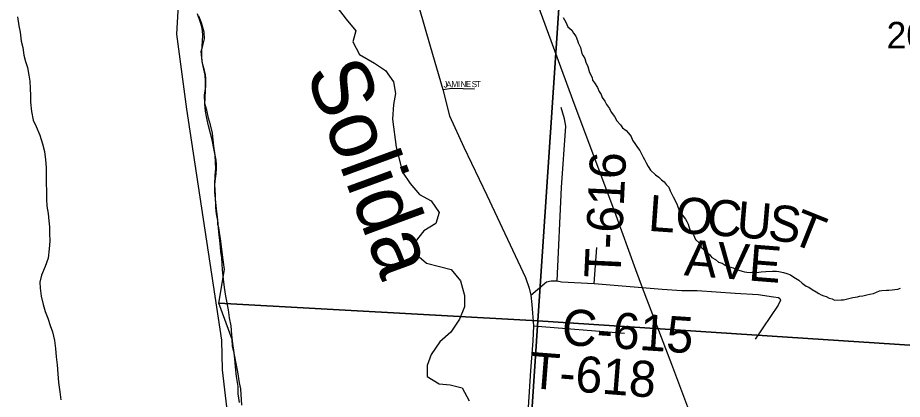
# Model space of a CAD drawing. Extents: x 1949938.81 to 1949945.61, y 152207.65 to 152214.09.
# Drawn here: x 1949939.476 to 1949940.868, y 152211.171 to 152211.771 of the extents above; entities that cross this region are included whole.
import ezdxf

# ---------------------------------------------------------------- set-up
doc = ezdxf.new("R2010")
doc.units = 0
for name, color, linetype in [('GM_X_County', 7, 'Continuous'), ('GM_X_County_Road', 7, 'Continuous'), ('GM_X_County_Road_Text', 7, 'Continuous'), ('GM_X_Major_River', 7, 'Continuous'), ('GM_X_Minor_River', 7, 'Continuous'), ('GM_X_Minor_River_Text', 7, 'Continuous'), ('GM_X_Section', 7, 'Continuous'), ('GM_X_Section_Text', 7, 'Continuous'), ('GM_X_Township', 7, 'Continuous'), ('GM_X_Township_Road', 7, 'Continuous'), ('GM_X_Township_Road_Text', 7, 'Continuous'), ('GM_X_Township_Subdivision', 7, 'Continuous'), ('GM_X_Township_Subdivision_Text', 7, 'Continuous'), ('GM_X_US_Route', 7, 'Continuous')]:
    doc.layers.add(name, color=color, linetype=linetype)

msp = doc.modelspace()

# ---------------------------------------------------------------- linework, layer by layer
at = {"layer": 'GM_X_County'}
msp.add_lwpolyline([(1949939.7311, 152211.8376), (1949939.7258, 152211.7457), (1949939.7413, 152211.6273), (1949939.7962, 152211.2639), (1949939.7977, 152211.2171), (1949939.8117, 152211.0959), (1949939.8776, 152210.6025), (1949939.8931, 152210.4482), (1949939.9215, 152210.363), (1949939.9378, 152210.2911), (1949940.0851, 152209.7125), (1949940.1207, 152209.6209), (1949940.3383, 152209.2145), (1949940.3947, 152209.1158)], dxfattribs=at)
at = {"layer": 'GM_X_County_Road'}
for points in [[(1949940.0902, 152211.8474), (1949940.1245, 152211.7264), (1949940.1446, 152211.6586), (1949940.1553, 152211.6171), (1949940.1779, 152211.5675), (1949940.2141, 152211.4924), (1949940.2747, 152211.3627), (1949940.2807, 152211.3456), (1949940.2832, 152211.3349), (1949940.2845, 152211.32), (1949940.2871, 152211.2866), (1949940.2865, 152211.2628), (1949940.2824, 152211.2159), (1949940.2737, 152211.0767), (1949940.2714, 152211.0147), (1949940.2658, 152210.896)], [(1949940.2832, 152211.3349), (1949940.3076, 152211.3557), (1949940.3151, 152211.3576), (1949940.3248, 152211.3574), (1949940.3316, 152211.3557), (1949940.3825, 152211.3532), (1949940.4583, 152211.3469)]]:
    msp.add_lwpolyline(points, dxfattribs=at)
at = {"layer": 'GM_X_Major_River'}
for points in [[(1949939.4757, 152211.7727), (1949939.4776, 152211.7586), (1949939.4795, 152211.7488), (1949939.4814, 152211.7344), (1949939.4837, 152211.7245), (1949939.4856, 152211.7127), (1949939.4882, 152211.7025), (1949939.4912, 152211.693), (1949939.4935, 152211.6812), (1949939.4946, 152211.6714), (1949939.4954, 152211.66), (1949939.4958, 152211.649), (1949939.4958, 152211.6384), (1949939.4976, 152211.6236), (1949939.5003, 152211.6103), (1949939.5048, 152211.6004), (1949939.5105, 152211.5867), (1949939.5146, 152211.5731), (1949939.5177, 152211.5609), (1949939.5196, 152211.5476), (1949939.5203, 152211.5359), (1949939.5203, 152211.5256), (1949939.5207, 152211.5097), (1949939.5211, 152211.4998), (1949939.5211, 152211.4865), (1949939.5218, 152211.4751), (1949939.5237, 152211.4634), (1949939.5248, 152211.452), (1949939.5256, 152211.4425), (1949939.526, 152211.4323), (1949939.5263, 152211.4197), (1949939.5252, 152211.4076), (1949939.5237, 152211.3932), (1949939.5191, 152211.3799), (1949939.5131, 152211.3662), (1949939.5108, 152211.3552), (1949939.5112, 152211.3457), (1949939.5127, 152211.3332), (1949939.5157, 152211.3199), (1949939.5191, 152211.3093), (1949939.5233, 152211.2986), (1949939.5271, 152211.2869), (1949939.5305, 152211.277), (1949939.5335, 152211.2637), (1949939.5354, 152211.2508), (1949939.5365, 152211.2379), (1949939.5376, 152211.2253), (1949939.5388, 152211.2109), (1949939.5399, 152211.1976), (1949939.5418, 152211.1828), (1949939.5437, 152211.1703)], [(1949939.8246, 152211.166), (1949939.8227, 152211.1793), (1949939.8224, 152211.1911), (1949939.8201, 152211.207), (1949939.8186, 152211.2218), (1949939.8175, 152211.2347), (1949939.8156, 152211.248), (1949939.8144, 152211.2587), (1949939.8129, 152211.2723), (1949939.8114, 152211.2868), (1949939.8092, 152211.2989), (1949939.8073, 152211.3118), (1949939.8031, 152211.3335), (1949939.8009, 152211.3471), (1949939.7993, 152211.36), (1949939.7982, 152211.3745), (1949939.7967, 152211.3934), (1949939.7956, 152211.4033), (1949939.7941, 152211.4162), (1949939.7922, 152211.4344), (1949939.7914, 152211.4477), (1949939.7903, 152211.458), (1949939.7888, 152211.4705), (1949939.7876, 152211.4804), (1949939.7861, 152211.4974), (1949939.7858, 152211.5092), (1949939.7865, 152211.5229), (1949939.7873, 152211.5343), (1949939.7869, 152211.5441), (1949939.7862, 152211.5551), (1949939.7846, 152211.5692), (1949939.7835, 152211.579), (1949939.782, 152211.5897), (1949939.779, 152211.6026), (1949939.776, 152211.6132), (1949939.7733, 152211.6257), (1949939.7703, 152211.6364), (1949939.7695, 152211.6493), (1949939.7711, 152211.6599), (1949939.7714, 152211.6716), (1949939.7707, 152211.6811), (1949939.7688, 152211.6906), (1949939.7661, 152211.7024), (1949939.7646, 152211.7183), (1949939.7673, 152211.7278), (1949939.7696, 152211.7384), (1949939.7692, 152211.7487), (1949939.765, 152211.7635), (1949939.7609, 152211.7741)]]:
    msp.add_lwpolyline(points, dxfattribs=at)
at = {"layer": 'GM_X_Minor_River'}
for points in [[(1949939.9784, 152211.7876), (1949939.9927, 152211.7693), (1949940.0077, 152211.751), (1949940.0031, 152211.7335), (1949940.0136, 152211.7138), (1949940.0371, 152211.7), (1949940.0544, 152211.6885), (1949940.0672, 152211.6703), (1949940.0702, 152211.652), (1949940.0671, 152211.6346), (1949940.0655, 152211.6118), (1949940.0714, 152211.5677), (1949940.081, 152211.5282), (1949940.0931, 152211.5107), (1949940.1082, 152211.4931), (1949940.1263, 152211.4832), (1949940.1391, 152211.4649), (1949940.1337, 152211.4474), (1949940.1147, 152211.4361), (1949940.101, 152211.4187), (1949940.1002, 152211.4012), (1949940.1191, 152211.3852), (1949940.1395, 152211.3798), (1949940.1577, 152211.3752), (1949940.1727, 152211.3576), (1949940.1787, 152211.3341), (1949940.1786, 152211.3166), (1949940.171, 152211.2969), (1949940.1573, 152211.2764), (1949940.1398, 152211.2613), (1949940.1261, 152211.2416), (1949940.1199, 152211.2241), (1949940.1199, 152211.2066), (1949940.1387, 152211.1952), (1949940.1562, 152211.1936), (1949940.1751, 152211.1889), (1949940.1863, 152211.1684)], [(1949940.3338, 152211.7719), (1949940.3382, 152211.7642), (1949940.3415, 152211.7573), (1949940.3475, 152211.7519), (1949940.3501, 152211.7469), (1949940.3541, 152211.7423), (1949940.3563, 152211.7358), (1949940.3574, 152211.732), (1949940.361, 152211.7243), (1949940.3635, 152211.7151), (1949940.3653, 152211.7117), (1949940.3679, 152211.7071), (1949940.3697, 152211.7013), (1949940.373, 152211.6948), (1949940.3755, 152211.6853), (1949940.3795, 152211.6772), (1949940.3802, 152211.6734), (1949940.3832, 152211.6692), (1949940.3879, 152211.6615), (1949940.3905, 152211.6554), (1949940.3938, 152211.6508), (1949940.3956, 152211.6458), (1949940.3997, 152211.64), (1949940.4022, 152211.6347), (1949940.4071, 152211.6285), (1949940.4096, 152211.6228), (1949940.4148, 152211.6162), (1949940.4185, 152211.6093), (1949940.424, 152211.6028), (1949940.4274, 152211.5982), (1949940.433, 152211.5939), (1949940.4367, 152211.5896), (1949940.4411, 152211.5846), (1949940.4433, 152211.5785), (1949940.4477, 152211.572), (1949940.4507, 152211.567), (1949940.4544, 152211.5624), (1949940.4566, 152211.5585), (1949940.4599, 152211.552), (1949940.4621, 152211.5485), (1949940.4646, 152211.5428), (1949940.4676, 152211.5371), (1949940.4713, 152211.5313), (1949940.4795, 152211.5243), (1949940.4843, 152211.5204), (1949940.4888, 152211.5162), (1949940.4929, 152211.5131), (1949940.4959, 152211.5092), (1949940.5, 152211.5046), (1949940.5021, 152211.4988), (1949940.5069, 152211.4896), (1949940.5095, 152211.485), (1949940.5131, 152211.477), (1949940.5164, 152211.4682), (1949940.523, 152211.4593), (1949940.5264, 152211.4543), (1949940.5286, 152211.4509), (1949940.5308, 152211.4463)], [(1949940.5308, 152211.4463), (1949940.5333, 152211.4375), (1949940.5388, 152211.4298), (1949940.5421, 152211.4225), (1949940.5473, 152211.4175), (1949940.5517, 152211.4098), (1949940.5569, 152211.4056), (1949940.561, 152211.4013), (1949940.5648, 152211.3982), (1949940.5681, 152211.394), (1949940.5737, 152211.3912), (1949940.5786, 152211.3869), (1949940.5842, 152211.3853), (1949940.5891, 152211.3822), (1949940.5959, 152211.3794), (1949940.6015, 152211.3778), (1949940.6102, 152211.3742), (1949940.6154, 152211.3726), (1949940.6192, 152211.3714), (1949940.623, 152211.371), (1949940.6294, 152211.3705), (1949940.6344, 152211.3708), (1949940.6378, 152211.3707), (1949940.6419, 152211.371), (1949940.6453, 152211.3714), (1949940.6526, 152211.372), (1949940.6632, 152211.3726), (1949940.6696, 152211.3725), (1949940.6734, 152211.372), (1949940.6809, 152211.3707), (1949940.6858, 152211.3688), (1949940.6915, 152211.3668), (1949940.6971, 152211.3629), (1949940.7046, 152211.3582), (1949940.7098, 152211.3539), (1949940.7165, 152211.3489), (1949940.7207, 152211.3473), (1949940.7255, 152211.3438), (1949940.7319, 152211.3402), (1949940.7364, 152211.3375), (1949940.7398, 152211.3355), (1949940.7443, 152211.3336), (1949940.7477, 152211.3327), (1949940.7526, 152211.33), (1949940.7571, 152211.3288), (1949940.7609, 152211.3272), (1949940.7715, 152211.3274), (1949940.7749, 152211.3277), (1949940.7836, 152211.3295), (1949940.7897, 152211.3313), (1949940.7969, 152211.3323), (1949940.8004, 152211.3334), (1949940.8057, 152211.334), (1949940.8118, 152211.3351), (1949940.8167, 152211.3365), (1949940.822, 152211.3375), (1949940.827, 152211.3394), (1949940.8316, 152211.3416), (1949940.8354, 152211.3423), (1949940.8429, 152211.3429), (1949940.8464, 152211.3428), (1949940.8517, 152211.3431), (1949940.8558, 152211.3438), (1949940.8604, 152211.3445), (1949940.8646, 152211.3456)]]:
    msp.add_lwpolyline(points, dxfattribs=at)
at = {"layer": 'GM_X_Section'}
for points in [[(1949940.3609, 152212.2864), (1949940.2943, 152211.2945), (1949939.792, 152211.3222), (1949939.8011, 152211.3752), (1949939.7992, 152211.3903), (1949939.7947, 152211.4237), (1949939.7935, 152211.4332), (1949939.792, 152211.4407), (1949939.7909, 152211.446), (1949939.7905, 152211.4521), (1949939.7886, 152211.4627), (1949939.7875, 152211.4729), (1949939.7868, 152211.4923), (1949939.786, 152211.5086), (1949939.7864, 152211.5142), (1949939.7879, 152211.5256), (1949939.7883, 152211.5343), (1949939.7883, 152211.5408), (1949939.7879, 152211.5472), (1949939.7857, 152211.5578), (1949939.7845, 152211.5658), (1949939.7815, 152211.5794), (1949939.7762, 152211.6014), (1949939.774, 152211.6105), (1949939.7728, 152211.6158), (1949939.7713, 152211.6245), (1949939.7702, 152211.6359), (1949939.7706, 152211.6446), (1949939.771, 152211.6582), (1949939.7717, 152211.6643), (1949939.7717, 152211.6707), (1949939.7717, 152211.676), (1949939.771, 152211.6817), (1949939.7695, 152211.6885), (1949939.7668, 152211.698), (1949939.7661, 152211.7033), (1949939.7657, 152211.7098), (1949939.7657, 152211.7181), (1949939.7669, 152211.7431), (1949939.7665, 152211.7514), (1949939.7657, 152211.7571), (1949939.7635, 152211.7639), (1949939.7589, 152211.7776)], [(1949939.8282, 152211.1619), (1949939.8267, 152211.1872), (1949939.8248, 152211.1967), (1949939.8222, 152211.2142), (1949939.8196, 152211.2274), (1949939.8162, 152211.2433), (1949939.8139, 152211.2543), (1949939.8131, 152211.2649), (1949939.792, 152211.3222), (1949940.2943, 152211.2945), (1949940.227, 152210.2792)]]:
    msp.add_lwpolyline(points, dxfattribs=at)
for points in [[(1949940.3609, 152212.2864), (1949941.4524, 152212.2232), (1949941.3926, 152211.2226), (1949940.2943, 152211.2945)], [(1949941.3926, 152211.2226), (1949941.3344, 152210.2133), (1949940.227, 152210.2792), (1949940.2943, 152211.2945)]]:
    msp.add_lwpolyline(points, close=True, dxfattribs=at)
at = {"layer": 'GM_X_Township'}
msp.add_lwpolyline([(1949939.7311, 152211.8376), (1949939.7258, 152211.7457), (1949939.7413, 152211.6273), (1949939.7962, 152211.2639), (1949939.7977, 152211.2171), (1949939.8117, 152211.0959), (1949939.8776, 152210.6025), (1949939.8931, 152210.4482), (1949939.9215, 152210.363), (1949939.9378, 152210.2911), (1949940.0851, 152209.7125), (1949940.1207, 152209.6209), (1949940.3383, 152209.2145), (1949940.3947, 152209.1158)], dxfattribs=at)
at = {"layer": 'GM_X_Township_Road'}
for points in [[(1949940.3248, 152211.3574), (1949940.3312, 152211.5043), (1949940.3381, 152211.6009), (1949940.3363, 152211.6123), (1949940.3308, 152211.6302)], [(1949940.3825, 152211.3532), (1949940.3867, 152211.4098)], [(1949940.4583, 152211.3469), (1949940.4899, 152211.344), (1949940.5209, 152211.3422), (1949940.5449, 152211.3419), (1949940.6048, 152211.3377), (1949940.6406, 152211.3356), (1949940.6647, 152211.3321), (1949940.6727, 152211.3314), (1949940.6748, 152211.3297), (1949940.6761, 152211.3272), (1949940.672, 152211.3189), (1949940.6361, 152211.2656)], [(1949940.2871, 152211.2866), (1949940.4303, 152211.2748)]]:
    msp.add_lwpolyline(points, dxfattribs=at)
at = {"layer": 'GM_X_Township_Subdivision'}
msp.add_lwpolyline([(1949940.1446, 152211.6586), (1949940.1586, 152211.6604), (1949940.1944, 152211.6597)], dxfattribs=at)
at = {"layer": 'GM_X_US_Route'}
for points in [[(1949940.0988, 152212.2209), (1949940.137, 152212.1578), (1949940.1603, 152212.1157), (1949940.1824, 152212.0725), (1949940.1941, 152212.0476), (1949940.211, 152212.006), (1949940.2326, 152211.9527), (1949940.2697, 152211.8588), (1949940.3524, 152211.6329), (1949940.4147, 152211.4664), (1949940.448, 152211.375)], [(1949940.448, 152211.375), (1949940.4583, 152211.3469), (1949940.5043, 152211.2261), (1949940.5628, 152211.0708), (1949940.5921, 152210.9937), (1949940.6917, 152210.7462), (1949940.7773, 152210.5432), (1949940.8719, 152210.3344), (1949940.9687, 152210.1169), (1949941.0372, 152209.9608), (1949941.0687, 152209.891)]]:
    msp.add_lwpolyline(points, dxfattribs=at)

# ---------------------------------------------------------------- texts
at = {"layer": 'GM_X_County_Road_Text'}
msp.add_text('C-615', height=0.05682, rotation=356.1656, dxfattribs=at).set_placement((1949940.3306, 152211.2569))
at = {"layer": 'GM_X_Minor_River_Text'}
msp.add_text('Solida', height=0.09473, rotation=290.1019, dxfattribs=at).set_placement((1949939.9284, 152211.6859))
at = {"layer": 'GM_X_Section_Text'}
msp.add_text('20', height=0.04186, rotation=0, dxfattribs=at).set_placement((1949940.8428, 152211.723))
at = {"layer": 'GM_X_Township_Road_Text'}
for s, height, rotation, p in [('T-616', 0.05682, 87.2565, (1949940.4238, 152211.3604)), ('L', 0.0568, 355.951, (1949940.4666, 152211.4362)), ('O', 0.0568, 355.9508, (1949940.509, 152211.4332)), ('C', 0.0568, 355.9506, (1949940.5588, 152211.4297)), ('U', 0.0568, 355.2079, (1949940.6052, 152211.4264)), ('S', 0.0568, 352.7483, (1949940.6544, 152211.4223)), ('T', 0.0568, 338.228, (1949940.6887, 152211.4184)), ('AVE', 0.05682, 355.4831, (1949940.5234, 152211.3661)), ('T-618', 0.05682, 355.5153, (1949940.2801, 152211.1888))]:
    msp.add_text(s, height=height, rotation=rotation, dxfattribs=at).set_placement(p)
at = {"layer": 'GM_X_Township_Subdivision_Text'}
for s, rotation, p in [('J', 3.7181, (1949940.146, 152211.6614)), ('A', 3.2368, (1949940.1501, 152211.6617)), ('M', 0.585, (1949940.1583, 152211.6621)), ('I', 0, (1949940.1683, 152211.6622)), ('N', 0, (1949940.1725, 152211.6622)), ('E', 0, (1949940.1808, 152211.6622)), ('S', 0, (1949940.19, 152211.6622)), ('T', 0, (1949940.1967, 152211.6622))]:
    msp.add_text(s, height=0.00947, rotation=rotation, dxfattribs=at).set_placement(p)

doc.saveas('drawing.dxf')
